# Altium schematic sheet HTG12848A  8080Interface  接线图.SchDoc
size A4
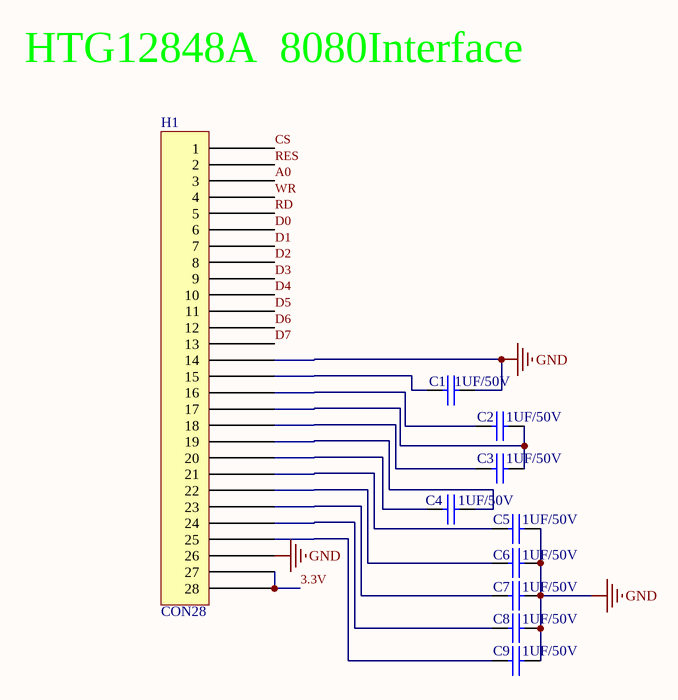
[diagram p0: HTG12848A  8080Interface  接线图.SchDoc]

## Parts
C1  1UF/50V  [0805CAP]
C2  1UF/50V  [0805CAP]
C3  1UF/50V  [0805CAP]
C4  1UF/50V  [0805CAP]
C5  1UF/50V  [0805CAP]
C6  1UF/50V  [0805CAP]
C7  1UF/50V  [0805CAP]
C8  1UF/50V  [0805CAP]
C9  1UF/50V  [0805CAP]
H1  CON28

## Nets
GND: C1.2 C5.2 C6.2 C7.2 C8.2 C9.2 H1.14 H1.26
3.3V: H1.27 H1.28
A0: H1.3
CS: H1.1
D0: H1.6
D1: H1.7
D2: H1.8
D3: H1.9
D4: H1.10
D5: H1.11
D6: H1.12
D7: H1.13
RD: H1.5
RES: H1.2
WR: H1.4
NetC1_1: C1.1 H1.15
NetC2_1: C2.1 H1.16
NetC2_2: C2.2 C3.2 H1.17
NetC3_1: C3.1 H1.18
NetC4_1: C4.1 H1.19
NetC4_2: C4.2 H1.20
NetC5_1: C5.1 H1.21
NetC6_1: C6.1 H1.22
NetC7_1: C7.1 H1.23
NetC8_1: C8.1 H1.24
NetC9_1: C9.1 H1.25

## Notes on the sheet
- HTG12848A  8080Interface

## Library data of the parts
C1-C9 = CAP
